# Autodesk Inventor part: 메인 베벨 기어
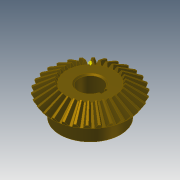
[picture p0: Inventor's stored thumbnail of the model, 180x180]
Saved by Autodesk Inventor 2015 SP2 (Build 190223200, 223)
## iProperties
Created: 2014-10
Part Number: 메인 베벨 기어
Material: 강철
Document SubType Name: Modeling
Designer: KYOUNG IL JANG
Categories: <?xml version="1.0" encoding="UTF-16"?> <MemberInstance><Categories><FamilyTemplate><FamilyTemplateParameter ValueType="xs:double" Id="1" ObjectReferenceKey="da
Mass: 269.24 g
Surface Area: 108.837 cm^2
Volume: 34.2981 cm^3
Density: 7.85 g/cm^3
Appearance: 얼룩무늬
CustomPartVersion: 1
Company: 한국ATC센터
Author: KYOUNG IL JANG
Revision Number: 1
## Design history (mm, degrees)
node "맨 위 점"
node "메쉬 평면2"
sketch "톱니 본체 스케치"
  geometry: L1 (0, 0)-(28.669, -21.997); L2 (28.669, -21.997)-(31.109, -18.336); L3 (31.109, -18.336)-(0, 0); L4 (30, -20)-(0, 0); L5 (17.219, -13.212)-(18.685, -11.013); L6 (28.669, -21.997)-(17.219, -13.212); L7 (31.109, -18.336)-(18.685, -11.013); L8 (0, -39.387)-(0, 6.564) reference; L9 (0, -20)-(31.109, -20)
  constraints: 16 end point, 4 point on line, 3 perpendicular, 2 collinear, 1 horizontal alignment, 1 vertical alignment
  dimensions: "d0" = 60 diameter of L4.start L8 (= da_de); "d1" = 57.33744 diameter of L1.end L8 (= da_dfe); "d2" = 62.2188 diameter of L2.end L8 (= da_dae); "d3" = 14.4 distance between parallel lines of L2 L5 (= da_b); "d4" = 18.3359 vertical distance of L2.end L1.start (= da_ve)
revolve "톱니 본체" sketch "톱니 본체 스케치" stored, may be unused: angle "d5" = 90 deg
node "시작점"
node "톱니 평면"
sketch "시작 스케치"
  geometry: L1 (0, -23.505)-(0, 10.645) reference; L2 (-0.709, -2.928)-(0.709, -2.928); A1 r 19.188 centre (-19.457, -7.014) between (-0.709, -2.928) and (-3.232, 3.229); A2 r 19.188 centre (19.457, -7.014) between (3.232, 3.229) and (0.709, -2.928); A3 r 57.403 centre (0, -54.083) between (3.232, 3.229) and (-3.232, 3.229); 1 further point
  constraints: 6 point on circle, 3 centre point, 3 symmetric about line, 2 end point, 1 coincident, 1 perpendicular, 1 other
  dimensions: "d7" = 19.18795 radius of A1 (= fd_rr); "d8" = 19.45712 horizontal distance of point (0, -54.083) A1.centre (= fd_x); "d9" = 47.06905 vertical distance of point (0, -54.083) A1.centre (= fd_y); "d57" = 57.40327 radius of A3 (= 0.5 x fd_dva + 0.3 x da_he); "d58" = 51.15527 distance from line of A3.centre L2 (= 0.5 x fd_dva - 1.12 x da_he)
node "끝점"
  node "끝 평면"
sketch "3D 스케치 오른쪽"
  node "Helical Curve Right" dims "d65" = 229.90621 (computed from da_dm, da_delta, da_beta), "d66" = 31.5, "d67" = 60 (= da_de), "d68" = -9.82794 (= -da_delta), "d69" = 8.10972 (computed from fd_loft, da_delta)
node "끝 평면 오른쪽"
sketch "끝 스케치 오른쪽"
  geometry: L1 (0, -41.54)-(0, 13.178) reference; L2 (-0.422, -1.69)-(0.422, -1.69); A1 r 11.427 centre (-11.587, -4.123) between (-0.422, -1.69) and (-1.925, 1.977); A2 r 11.427 centre (11.587, -4.123) between (1.925, 1.977) and (0.422, -1.69); A3 r 34.184 centre (0, -32.153) between (1.925, 1.977) and (-1.925, 1.977); 1 further point
  constraints: 6 point on circle, 3 centre point, 3 symmetric about line, 2 end point, 1 coincident, 1 perpendicular, 1 other
  dimensions: "d70" = 11.58699 horizontal distance of A3.centre A1.centre (computed from fd_x, fd_ratio); "d71" = 28.03028 vertical distance of point (0, -32.153) A1.centre (computed from fd_y, fd_ratio); "d72" = 11.4267 radius of A1 (computed from fd_rr, fd_ratio); "d73" = 30.46369 distance from line of point (0, -32.153) L2 (computed from d58, fd_ratio); "d74" = 34.18446 radius of A3 (computed from d57, fd_ratio)
feature "로프트 오른쪽" sketch "끝 스케치 오른쪽" dims "d75" = 0, "d77" = 0, "d79" = 0, "d80" = 90 deg, "d85" = 20, "d92" = 90 deg, "d93" = 90 deg, "da_teethtype" = 0 [user parameter]
sketch "3D 스케치 왼쪽"
  node "Helical Curve Left" dims "d26" = 229.90621 (computed from da_dm, da_delta, da_beta), "d27" = 8.10972 (computed from fd_loft, da_delta), "d28" = 60 (= da_de), "d29" = -9.82794 (= -da_delta)
node "끝 평면 왼쪽"
sketch "끝 스케치 왼쪽" dims "d56" = 10.3728 (derived)
  geometry: L1 (0, -43.753)-(0, 15.405) reference; L2 (-0.422, -1.678)-(0.422, -1.678); A1 r 11.427 centre (-11.587, -4.111) between (-0.422, -1.678) and (-1.925, 1.988); A2 r 11.427 centre (11.587, -4.111) between (1.925, 1.988) and (0.422, -1.678); A3 r 34.184 centre (0, -32.142) between (1.925, 1.988) and (-1.925, 1.988); 2 further points; 1 other entity
  constraints: 6 point on circle, 3 centre point, 3 symmetric about line, 2 end point, 1 coincident, 2 other
  dimensions: "d30" = 11.4267 radius of A1 (computed from fd_rr, fd_ratio); "d31" = 11.58699 horizontal distance of point (0, -32.142) A1.centre (computed from fd_x, fd_ratio); "d32" = 28.03028 vertical distance of A1.centre point (0, -32.142) (computed from fd_y, fd_ratio); "d61" = 34.18446 radius of A3 (computed from d57, fd_ratio); "d62" = 30.46369 distance from line of point (0, -32.142) L2 (computed from d58, fd_ratio)
feature "로프트 왼쪽" sketch "끝 스케치 왼쪽" dims "d35" = 0, "d37" = 0, "d39" = 0, "d40" = 90 deg, "d84" = 10, "d90" = 90 deg, "d91" = 90 deg, "da_teethtype" = 0 [user parameter]
sketch "본체 스케치"
  geometry: L1 (0, -35.038)-(0, -19.531) reference; L2 (28.669, -21.997)-(17.219, -13.212) reference; L3 (17.219, -13.212)-(0, -13.212); L4 (28.669, -21.997)-(0, -21.997)
  constraints: 4 end point, 2 perpendicular, 2 point on line
revolve "본체 고정" sketch "본체 스케치" stored, may be unused: angle "d46" = 90 deg
feature "피치 지름" dims angle "d47" = 90 deg
sketch "스케치8"
  geometry: C1 r 22.5 at (0, 0); 1 further point
  constraints: 1 centre point, 1 coincident
  dimensions: "d94" = 45 diameter of C1
extrude "돌출1" join sketch "스케치8" distance "d95" = 13; taper "d96" = 0 deg
sketch "스케치9"
  geometry: 1 further point
hole "구멍1" sketch "스케치9" at (0, 0) diameter "d97" = 17; stored, may be unused: countersink angle "d101" = 90 deg, drill point angle "d103" = 118 deg; dims "d98" = 6, "d99" = 4, "d100" = 2, "d102" = 8
sketch "스케치10"
  geometry: L1 (8.124, 2.5)-(10.8, 2.5); L2 (10.8, 2.5)-(10.8, -2.5); L3 (10.8, -2.5)-(8.124, -2.5); A1 r 8.5 centre (0, 0) between (8.124, 2.5) and (8.124, -2.5) reference; 1 further point
  constraints: 6 end point, 2 parallel, 2 point on circle, 1 horizontal, 1 perpendicular
  dimensions: "d104" = 5 distance of L1.end L2.end; "d112" = 19.3 dimension on A1 L2
extrude "돌출2" cut sketch "스케치10" stored distance "d106" = 10; taper "d107" = 0 deg
chamfer "모따기1" distance "d108" = 1; stored, may be unused: second distance "d109" = 2, angle "d110" = 45 deg
fillet "모깎기1" dims "d111" = 2
body "Solid1"
feature "로프트" dims "d17" = 0, "d18" = 90 deg, "d19" = 0, "d20" = 90 deg, "d89" = 0, "da_teethtype" = 0 [user parameter]
pattern_circular "원형 패턴" dims angle "d22" = 360 deg, "d88" = 0, "da_teethtype" = 0 [user parameter]
pattern_circular "원형 패턴 오른쪽" dims angle "d82" = 360 deg, "da_teethtype" = 0 [user parameter]
pattern_circular "원형 패턴 왼쪽" dims angle "d42" = 360 deg, "da_teethtype" = 0 [user parameter]
sketch "끝 스케치"
  geometry: L1 (0, -15.359)-(0, 6.983) reference; L2 (-0.422, -1.69)-(0.422, -1.69); A1 r 11.427 centre (-11.587, -4.123) between (-0.422, -1.69) and (-1.925, 1.977); A2 r 11.427 centre (11.587, -4.123) between (1.925, 1.977) and (0.422, -1.69); A3 r 34.184 centre (0, -32.153) between (1.925, 1.977) and (-1.925, 1.977); 1 further point
  constraints: 6 point on circle, 3 centre point, 3 symmetric about line, 2 end point, 1 coincident, 1 other
  dimensions: "d12" = 11.4267 radius of A1 (computed from fd_rr, fd_ratio); "d15" = 11.58699 horizontal distance of A1.centre point (0, -32.153) (computed from fd_x, fd_ratio); "d16" = 28.03028 vertical distance of A1.centre point (0, -32.153) (computed from fd_y, fd_ratio); "d59" = 34.18446 radius of A3 (computed from d57, fd_ratio); "d60" = 30.46369 distance from line of A3.centre L2 (computed from d58, fd_ratio)
sketch "Sketch6"
  geometry: L1 (30, -20)-(0, 0) reference; L2 (0, -37.8)-(0, 6.3) reference
body "Srf1"
other parameters: "da_b" = 14.4 [user parameter; used in 2 equation terms], "da_de" = 60 [user parameter; used in 4 equation terms], "da_dae" = 62.2188 [user parameter; used in 2 equation terms], "da_dfe" = 57.33744 [user parameter; used in 1 equation term], "da_le" = 36.05551 [user parameter; used in 1 equation term], "da_omega" = 90 deg [user parameter; used in 1 equation term], "da_beta" = 0 [user parameter; used in 2 equation terms], "da_delta" = 9.82794 [user parameter; used in 8 equation terms], "da_alpha" = 20 deg [user parameter; used in 2 equation terms], "da_he" = 4.4 [user parameter; used in 4 equation terms], "da_ve" = 18.3359 [user parameter; used in 1 equation term], "fd_dv" = 108.16654 (computed from da_de, da_delta) [user parameter; used in 1 equation term], "fd_dva" = 112.16654 (computed from da_dae, da_delta) [user parameter; used in 3 equation terms], "fd_dvb" = 101.6433 (computed from fd_dv, da_alpha) [user parameter; used in 2 equation terms], "da_zv" = 540.83269 [user parameter; used in 1 equation term], "fd_loft" = 14.62 (= da_b + 0.05 x da_he) [user parameter; used in 4 equation terms], "fd_ratio" = 5.95514 (computed from da_le, fd_loft) [user parameter; used in 15 equation terms], "fd_rr" = 19.18795 (computed from fd_dd, fd_dvb) [user parameter; used in 6 equation terms], "fd_angle" = 0.29367 (computed from da_zv) [user parameter; used in 4 equation terms], "fd_x1" = 1.58802 (computed from da_dvw, fd_angle) [user parameter; used in 1 equation term], "fd_y1" = 54.05995 (computed from da_dvw, fd_angle) [user parameter; used in 1 equation term], "fd_x2" = 17.8691 (computed from fd_rr, fd_angle2, fd_angle) [user parameter; used in 1 equation term], "fd_y2" = 6.9909 (computed from fd_rr, fd_angle2, fd_angle) [user parameter; used in 1 equation term], "fd_x" = 19.45712 (= fd_x1 + fd_x2) [user parameter; used in 4 equation terms], "fd_y" = 47.06905 (= fd_y1 - fd_y2) [user parameter; used in 4 equation terms], "fd_angle2" = 3.43555 (computed from fd_dvb, fd_dd, da_alpha) [user parameter; used in 2 equation terms], "fd_dd" = 108.64654 (= fd_dva - 0.8 x da_he) [user parameter; used in 2 equation terms], "da_dvw" = 108.16654 [user parameter; used in 2 equation terms], "d11" = 14.62 (= fd_loft), "da_dm" = 48.01848 [user parameter; used in 2 equation terms], "da_x" = 0 [user parameter], "da_m" = 2 [user parameter], "d48" = 0, "d49" = 0, "d50" = 90 deg (= da_omega), "d51" = 6 deg (computed from da_z), "d52" = 0, "d53" = 0, "d54" = 0
